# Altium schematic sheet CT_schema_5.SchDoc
size 211 x 163 mm
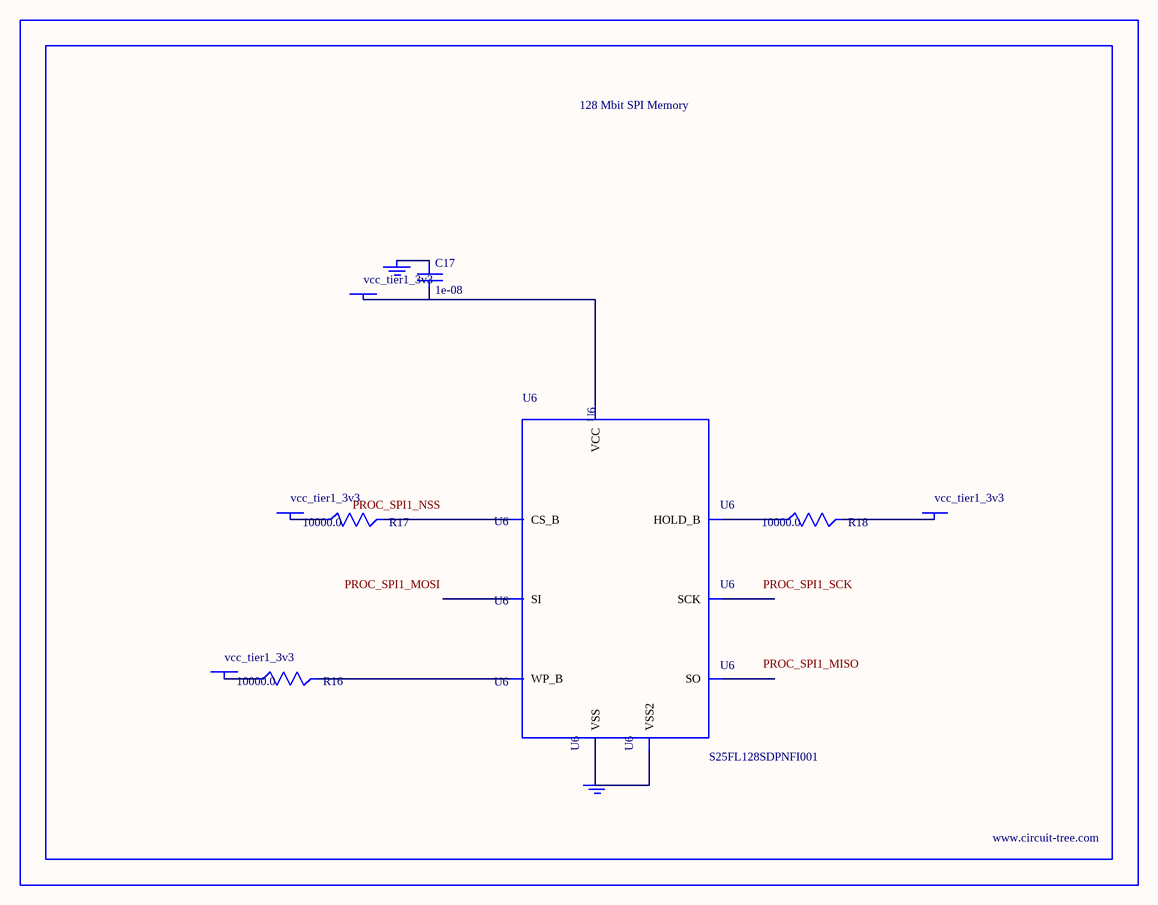
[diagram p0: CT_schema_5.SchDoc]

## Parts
BORDER4  (no value)
C17  1e-08  [C0402]
GND_INSTANCE_4_0  (no value)
GND_INSTANCE_4_1  (no value)
POWER_INSTANCE_4_0  vcc_tier1_3v3
POWER_INSTANCE_4_1  vcc_tier1_3v3
POWER_INSTANCE_4_2  vcc_tier1_3v3
POWER_INSTANCE_4_3  vcc_tier1_3v3
R16  10000.0  [R0603]
R17  10000.0  [R0603]
R18  10000.0  [R0603]
U6  S25FL128SDPNFI001  [WNG008]

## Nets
NetC17_1: C17.1 GND_INSTANCE_4_0.0(GND)
NetC17_2: C17.2 POWER_INSTANCE_4_3.0(PWR) U6.8(VCC)
NetGND_INSTANCE_4_1_0: GND_INSTANCE_4_1.0(GND) U6.4(VSS) U6.PAD(VSS2)
NetPOWER_INSTANCE_4_0_0: POWER_INSTANCE_4_0.0(PWR) R17.1
NetPOWER_INSTANCE_4_1_0: POWER_INSTANCE_4_1.0(PWR) R16.1
NetPOWER_INSTANCE_4_2_0: POWER_INSTANCE_4_2.0(PWR) R18.2
NetR16_2: R16.2 U6.3(WP_B)
NetR17_2: R17.2 U6.1(CS_B)
NetR18_1: R18.1 U6.7(HOLD_B)

Not connected (* = marked no-connect by the designer): U6 2(SO) 5(SI) 6(SCK)

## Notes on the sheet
- Labels drawn without touching a wire or pin: PROC_SPI1_MISO, PROC_SPI1_MOSI, PROC_SPI1_NSS, PROC_SPI1_SCK

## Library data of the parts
BORDER4 = BORDER_PAGE4
C17 = C0402C103K3RAC
GND_INSTANCE_4_0 GND_INSTANCE_4_1 = GND
POWER_INSTANCE_4_0-POWER_INSTANCE_4_3 = PWR
R16-R18 = RC0603JR-0710KL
